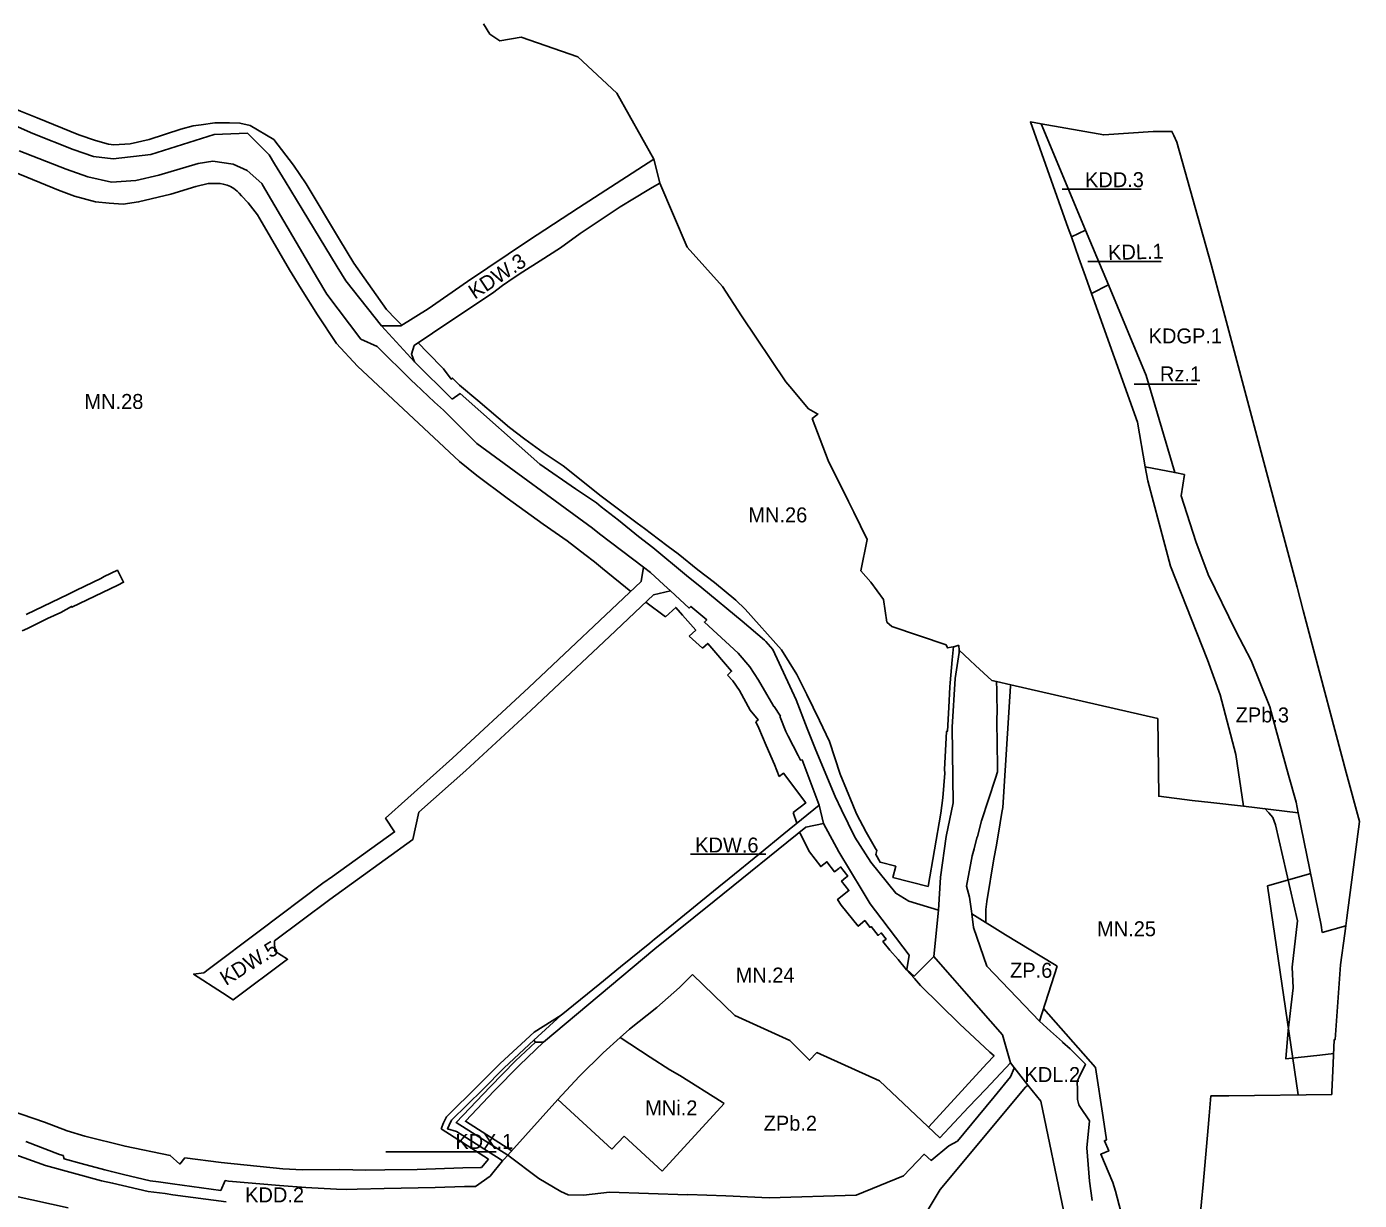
# Model space of a CAD drawing. Extents: x 7418991 to 7423142, y 5547704 to 5549547.
# Drawn here: x 7420035 to 7420480.5, y 5548551.2 to 5548943.4 of the extents above; entities that cross this region are included whole.
import ezdxf

# ---------------------------------------------------------------- set-up
doc = ezdxf.new("R2010")
doc.units = 0
for name, color, linetype in [('LIN_Linia Zabudowy Nieprzekraczalna', 7, 'Continuous'), ('LIN_linie_rozgraniczajace', 7, 'Continuous'), ('TRS_strefa ograniczen tunelu', 7, 'Continuous'), ('TXT_Oznaczenia_przeznaczen', 7, 'Continuous')]:
    doc.layers.add(name, color=color, linetype=linetype)

msp = doc.modelspace()

# ---------------------------------------------------------------- linework, layer by layer
at = {"layer": 'LIN_Linia Zabudowy Nieprzekraczalna'}
for p, q in [((7420248.59, 5548746.21), (7420241.92, 5548751.14)), ((7420260.87, 5548735.77), (7420256.47, 5548739.74)), ((7420279.77, 5548709.01), (7420278.76, 5548711.18)), ((7420282.17, 5548703.2), (7420279.77, 5548709.01)), ((7420292.45, 5548677.22), (7420291.24, 5548680.8)), ((7420189.36, 5548565.02), (7420173.52, 5548575.16)), ((7420187.02, 5548562.15), (7420189.36, 5548565.02))]:
    msp.add_line(p, q, dxfattribs=at)
for points in [[(7420022.61, 5548919.58), (7420030.2, 5548916.29), (7420032.93, 5548915.22), (7420038.5, 5548912.93), (7420052.44, 5548907.31), (7420057.96, 5548905.38), (7420062.32, 5548904.19), (7420064.15, 5548903.97), (7420069.56, 5548904.31), (7420075.9, 5548905.75), (7420086.49, 5548909.16)], [(7420086.49, 5548909.16), (7420090.64, 5548910.3), (7420093.26, 5548910.63), (7420097.86, 5548911.26), (7420102.81, 5548911.34), (7420106.29, 5548911.2), (7420109.65, 5548910.43), (7420117.58, 5548905.77)], [(7420117.58, 5548905.77), (7420124.15, 5548897.13), (7420128.46, 5548890.88), (7420139.53, 5548872.3), (7420144.32, 5548864.36)], [(7420236.92, 5548754.73), (7420227.53, 5548762.42), (7420224.79, 5548764.61), (7420221.57, 5548767.04), (7420215.71, 5548771.57), (7420207.67, 5548777.24), (7420195.64, 5548785.92), (7420185.42, 5548793.43), (7420179.71, 5548798.13), (7420145.56, 5548829.95), (7420138.55, 5548837.52), (7420132.23, 5548847.16), (7420126.76, 5548855.88), (7420122.8, 5548862.23), (7420112.91, 5548879.23), (7420112.11, 5548880.56), (7420108.98, 5548884.6), (7420106.82, 5548886.86), (7420106.04, 5548887.83), (7420105.36, 5548888.5), (7420104.28, 5548889.32), (7420103.16, 5548889.98), (7420101.95, 5548890.49), (7420100.7, 5548890.86), (7420099.62, 5548891.02), (7420095.7, 5548890.98), (7420091.48, 5548890.08), (7420083.16, 5548887.5), (7420072.38, 5548884.86), (7420067.26, 5548884.14), (7420062.54, 5548884.43), (7420057.96, 5548884.92), (7420050.94, 5548886.83), (7420045.62, 5548888.77), (7420026.39, 5548896.72)], [(7420144.32, 5548864.36), (7420155.26, 5548848.93), (7420158.44, 5548845.7), (7420160.37, 5548843.66)], [(7420165.88, 5548837.84), (7420168.98, 5548834.57), (7420174.34, 5548829.08), (7420176.89, 5548825.7), (7420177.33, 5548826.02), (7420179.62, 5548823.65), (7420185.78, 5548818.53), (7420192.55, 5548812.67), (7420196.43, 5548809.47), (7420201.46, 5548805.64), (7420207.68, 5548801.17), (7420214.3, 5548796.66), (7420227.06, 5548786.56), (7420239.03, 5548777.55), (7420241.49, 5548775.74), (7420246.15, 5548772.18), (7420249.46, 5548769.68), (7420252.73, 5548767.22), (7420259.32, 5548761.88), (7420264.92, 5548757.66), (7420272.01, 5548751.75), (7420275.13, 5548748.79), (7420287.28, 5548735.23), (7420292.47, 5548726.92), (7420295.81, 5548720.21), (7420300.03, 5548711.57), (7420303.32, 5548704.54), (7420306.92, 5548693.59), (7420311.16, 5548683.44), (7420312.39, 5548680.35), (7420315.62, 5548674.23), (7420318.68, 5548668.85), (7420319.15, 5548668.16)], [(7420256.47, 5548739.74), (7420258.63, 5548741.76), (7420254.17, 5548746.83), (7420251.96, 5548749.34), (7420248.59, 5548746.21)], [(7420269.22, 5548726.77), (7420270.65, 5548728.02), (7420262.67, 5548737.31), (7420260.87, 5548735.77)], [(7420336.39, 5548656.15), (7420340.59, 5548680.57), (7420341.25, 5548685.72), (7420341.92, 5548693.92), (7420341.85, 5548695.15), (7420342.47, 5548707.85), (7420342.78, 5548707.98), (7420343.21, 5548715.97), (7420343.57, 5548722.86), (7420343.67, 5548724.18), (7420344.39, 5548731.8), (7420344.85, 5548736.27)], [(7420276.86, 5548715.01), (7420273.32, 5548721.58), (7420271.01, 5548724.8), (7420269.22, 5548726.77)], [(7420363.94, 5548723.48), (7420363.91, 5548723.07), (7420363.67, 5548719.63), (7420361.35, 5548682.45), (7420361.18, 5548681.97), (7420361, 5548680.85), (7420360.45, 5548677.42), (7420359.24, 5548669.9), (7420358.29, 5548665.3), (7420355.94, 5548651.12), (7420355.59, 5548648.46), (7420355.63, 5548643.99)], [(7420278.76, 5548711.18), (7420279.49, 5548711.78), (7420276.86, 5548715.01)], [(7420286.52, 5548692.89), (7420285, 5548696.86), (7420282.17, 5548703.2)], [(7420291.24, 5548680.8), (7420295.43, 5548684.05), (7420287.93, 5548694.02), (7420286.52, 5548692.89)], [(7420471.99, 5548600.26), (7420467.24, 5548599.73), (7420455.92, 5548598.48), (7420456.74, 5548607.93), (7420458.33, 5548622.27), (7420458.04, 5548629.11), (7420459.76, 5548644.67), (7420452.41, 5548676.74), (7420451.53, 5548679.19), (7420450.27, 5548680.73), (7420448.77, 5548682.28)], [(7420336.48, 5548575.68), (7420341.46, 5548581.13), (7420355.97, 5548596.92), (7420358.35, 5548599.49), (7420356.98, 5548600.74), (7420346.77, 5548610.23), (7420333.74, 5548622.99), (7420331.74, 5548625.35), (7420329.14, 5548628.26), (7420326.32, 5548631.65), (7420323.48, 5548634.82), (7420321.22, 5548637.68), (7420322.29, 5548638.52), (7420320.63, 5548640.58), (7420319.6, 5548639.74), (7420317.24, 5548642.72), (7420316.93, 5548642.43), (7420315.16, 5548644.68), (7420312.99, 5548642.83), (7420307.26, 5548649.87), (7420306.08, 5548651.76), (7420309.85, 5548654.73), (7420307.38, 5548657.9), (7420308.85, 5548659.07), (7420309.47, 5548659.56), (7420307.08, 5548662.63), (7420306.44, 5548662.14), (7420304.98, 5548661.02), (7420302.48, 5548664.36), (7420300.43, 5548662.78), (7420296.68, 5548667.64), (7420293.59, 5548673.85), (7420293.43, 5548674.3)], [(7420319.15, 5548668.16), (7420318.8, 5548666.75), (7420320.26, 5548664.22), (7420325.51, 5548662.88), (7420324.57, 5548659.09), (7420336.39, 5548656.15)], [(7420173.52, 5548575.16), (7420174.36, 5548577.12), (7420175.28, 5548579.16), (7420186.04, 5548589.68), (7420193.23, 5548596.92), (7420204.59, 5548607.45), (7420213.62, 5548613.09)], [(7420374.87, 5548615.32), (7420392.3, 5548595.58), (7420394.85, 5548578.9), (7420395.98, 5548571.46), (7420395.24, 5548571.14), (7420396.71, 5548567.74), (7420394.04, 5548566.59), (7420398.11, 5548557.14), (7420398.97, 5548554.26), (7420402.53, 5548540.72), (7420403.2, 5548538.9), (7420404.26, 5548536.65), (7420405.58, 5548534.97), (7420408.13, 5548532.08), (7420410.13, 5548530.34), (7420410.95, 5548529.8), (7420423.29, 5548523.41), (7420431.15, 5548519.58), (7420439.54, 5548515.56)], [(7420207.72, 5548604.08), (7420199.75, 5548596.41), (7420191.31, 5548587.79), (7420181.67, 5548577.65), (7420197.14, 5548567.79)], [(7419981.5, 5548600.8), (7419992.1, 5548595.34), (7419997.1, 5548592.94), (7419998.04, 5548592.5), (7420006.38, 5548589.15), (7420010.64, 5548587.74), (7420040.89, 5548577.34), (7420048.53, 5548574.46), (7420054.4, 5548572.62), (7420067.89, 5548569.27), (7420082.96, 5548566.23), (7420086.13, 5548563.32), (7420087.87, 5548565.39), (7420099.95, 5548563.83)], [(7420099.95, 5548563.83), (7420120.62, 5548561.78), (7420127.14, 5548561.46), (7420139.62, 5548561.49), (7420148.34, 5548561.26), (7420154.7, 5548561.39), (7420165.51, 5548561.52), (7420180.8, 5548562.04), (7420186.64, 5548562.15), (7420187.02, 5548562.15)]]:
    msp.add_lwpolyline(points, dxfattribs=at)
at = {"layer": 'LIN_linie_rozgraniczajace'}
for p, q in [((7420032.47, 5548901.95), (7420048.13, 5548895.81)), ((7420048.13, 5548895.81), (7420055.41, 5548893.29)), ((7420071.43, 5548892.07), (7420079.12, 5548893.83)), ((7420055.41, 5548893.29), (7420063.37, 5548891.52)), ((7420063.37, 5548891.52), (7420071.43, 5548892.07)), ((7420113.57, 5548890.98), (7420113.82, 5548890.56)), ((7420113.82, 5548890.56), (7420132.24, 5548859.34)), ((7420384.22, 5548873.2), (7420388.96, 5548875.45)), ((7420132.24, 5548859.34), (7420135.36, 5548854.02)), ((7420135.36, 5548854.02), (7420146.74, 5548838.99)), ((7420390.96, 5548854.26), (7420396.59, 5548857.14)), ((7420153.63, 5548843.45), (7420160.03, 5548843.45)), ((7420146.74, 5548838.99), (7420152.16, 5548836.55)), ((7420418.77, 5548794.4), (7420408.9, 5548796.36)), ((7420241.14, 5548762.84), (7420240.4, 5548758.01)), ((7420244.49, 5548753.59), (7420250.2, 5548754.91)), ((7420460.03, 5548680.77), (7420441.72, 5548682.92)), ((7420136.31, 5548651.73), (7420117.84, 5548637.93)), ((7420339.78, 5548648.18), (7420338.24, 5548632.71)), ((7420475.96, 5548642.93), (7420468.03, 5548640.7)), ((7420117.84, 5548637.93), (7420117.98, 5548634.49)), ((7420204.57, 5548604.7), (7420205.11, 5548604.11)), ((7420365.01, 5548595.69), (7420363.87, 5548597.13)), ((7420369.71, 5548589.74), (7420365.01, 5548595.69)), ((7420386.84, 5548592.42), (7420386.15, 5548591.01)), ((7420212.59, 5548584.86), (7420230.62, 5548568.28)), ((7420247.38, 5548560.98), (7420268.14, 5548583.6)), ((7420230.62, 5548568.28), (7420234.7, 5548572.71)), ((7420234.7, 5548572.71), (7420247.38, 5548560.98)), ((7420099.84, 5548554.53), (7420101.33, 5548557.81)), ((7420101.33, 5548557.81), (7420102.41, 5548557.67)), ((7420048.85, 5548548.76), (7420031.14, 5548552.63)), ((7420268.75, 5548552.67), (7420256.05, 5548553.17)), ((7420283.14, 5548552.09), (7420268.75, 5548552.67))]:
    msp.add_line(p, q, dxfattribs=at)
for points in [[(7420187.72, 5548944.36), (7420189.78, 5548940.99), (7420193.14, 5548938.75), (7420200.25, 5548939.92), (7420219.25, 5548933.4), (7420232.28, 5548921.23), (7420244.58, 5548899.15), (7420246.62, 5548891.21), (7420246.63, 5548891.19), (7420255.83, 5548869.73), (7420267.57, 5548856.66), (7420273.97, 5548846.79), (7420288.8, 5548824.73), (7420290.08, 5548823.2), (7420296.36, 5548815.74), (7420299.51, 5548814), (7420297.61, 5548812.46), (7420302.96, 5548798.43), (7420309.68, 5548784.74), (7420311.45, 5548781.16), (7420315.91, 5548772.05), (7420313.83, 5548761.61), (7420317.22, 5548757.83), (7420321.41, 5548752.03), (7420322.5, 5548744.47), (7420324.15, 5548742.96), (7420342.32, 5548736.89), (7420342.75, 5548735.82), (7420345.23, 5548736.35), (7420346.3, 5548736.6), (7420346.62, 5548736.6), (7420346.67, 5548735.03), (7420350.29, 5548731.69), (7420352.15, 5548729.97), (7420357.63, 5548724.93), (7420359.15, 5548724.58), (7420363.94, 5548723.48), (7420413.08, 5548712.23), (7420413.45, 5548686.24), (7420424.58, 5548684.83), (7420430.85, 5548684.19), (7420441.72, 5548682.92), (7420439.14, 5548700.25), (7420433.98, 5548720.15), (7420429.76, 5548731.89), (7420417.31, 5548763.11), (7420417.31, 5548763.11), (7420409.72, 5548791.72), (7420408.9, 5548796.36), (7420406.28, 5548811.26), (7420390.96, 5548854.26), (7420388.92, 5548859.99), (7420386.74, 5548866.12), (7420384.22, 5548873.2), (7420383.17, 5548876.14), (7420370.54, 5548911.59), (7420374.15, 5548910.95), (7420395.06, 5548907.27), (7420411.6, 5548908.46), (7420417.81, 5548908.42), (7420418.45, 5548907.04), (7420419.49, 5548904.8), (7420430.95, 5548863.92), (7420434.62, 5548850.15), (7420459.65, 5548756.08), (7420461.72, 5548748.31), (7420463.74, 5548740.73), (7420476.12, 5548694.19), (7420480.48, 5548677.81), (7420476.31, 5548645.63), (7420475.96, 5548642.93), (7420475.63, 5548640.42), (7420474.14, 5548629.87), (7420472.37, 5548604.94), (7420472.09, 5548604.89), (7420471.59, 5548594.46), (7420471.31, 5548587.49), (7420471.27, 5548586.6), (7420436.83, 5548586.17), (7420430.86, 5548586.1), (7420430.26, 5548579.42), (7420429.92, 5548575.61), (7420428.22, 5548556.56), (7420427.18, 5548544.91)], [(7420037, 5548907.69), (7419994.04, 5548926.74), (7419977.79, 5548933.93), (7419969.89, 5548935.8), (7419962.51, 5548936.47), (7419951.22, 5548935.66), (7419947.24, 5548934.87)], [(7420037, 5548907.69), (7420050.55, 5548902.38), (7420057.32, 5548900.04)], [(7420057.32, 5548900.04), (7420063.93, 5548899.3), (7420076.53, 5548900.76), (7420097.7, 5548907.38), (7420108.81, 5548907.84)], [(7420108.81, 5548907.84), (7420110.02, 5548906.63), (7420115.99, 5548900.64), (7420117.78, 5548897.61)], [(7420468.03, 5548640.7), (7420467.73, 5548643.22), (7420460.03, 5548680.77), (7420459.32, 5548684.23), (7420456.84, 5548693.25), (7420454.73, 5548700.95), (7420452.61, 5548708.66), (7420450.57, 5548716.11), (7420444.3, 5548731.65), (7420439.24, 5548741.39), (7420429.92, 5548760.39), (7420425.8, 5548771.39), (7420420.93, 5548786.61), (7420422.03, 5548793.75), (7420418.77, 5548794.4), (7420409.2, 5548826.91), (7420396.59, 5548857.14), (7420392.74, 5548866.38), (7420388.96, 5548875.45), (7420374.15, 5548910.95)], [(7420113.57, 5548890.98), (7420108.74, 5548895.33), (7420104.05, 5548897.53), (7420097.23, 5548898.46), (7420092.34, 5548897.69), (7420079.12, 5548893.83)], [(7420160.03, 5548843.45), (7420169.18, 5548849.14), (7420182.39, 5548858.31), (7420202.69, 5548871.97), (7420219.47, 5548882.86), (7420244.58, 5548899.15)], [(7420164.68, 5548831.41), (7420153.63, 5548843.45), (7420141.63, 5548858.52), (7420138.74, 5548863.19), (7420127.05, 5548882.46), (7420121.43, 5548891.85), (7420117.78, 5548897.61)], [(7420164.54, 5548836.94), (7420176.81, 5548845.15), (7420190.74, 5548854.41), (7420194.1, 5548856.97), (7420197.94, 5548859.57), (7420200.82, 5548861.46), (7420206.59, 5548865.14), (7420213.4, 5548869.48), (7420219.96, 5548874.32), (7420224.4, 5548877.18), (7420233.35, 5548883.19), (7420238.21, 5548886.17), (7420242.38, 5548888.71), (7420244.06, 5548889.73), (7420246.63, 5548891.19)], [(7420152.16, 5548836.55), (7420163.64, 5548825.25), (7420164.97, 5548823.99), (7420171.34, 5548817.99), (7420174.3, 5548815.34), (7420185.48, 5548804.12)], [(7420164.68, 5548831.41), (7420163.67, 5548834), (7420164.54, 5548836.94)], [(7420164.68, 5548831.41), (7420177.22, 5548818.99)], [(7420206.51, 5548797.28), (7420179.92, 5548820.8), (7420177.22, 5548818.99)], [(7420248, 5548756.94), (7420243.57, 5548761), (7420241.14, 5548762.84), (7420226.5, 5548773.91), (7420224.14, 5548775.84), (7420185.48, 5548804.12)], [(7420206.51, 5548797.28), (7420218.48, 5548788.98), (7420225.45, 5548784.31), (7420227.02, 5548783.01), (7420232.77, 5548778.49), (7420239.47, 5548773.12), (7420244.25, 5548769.4)], [(7420281.62, 5548738.38), (7420274.2, 5548744.73), (7420260.65, 5548755.88), (7420255.52, 5548760.05), (7420244.25, 5548769.4)], [(7420033.45, 5548741.57), (7420035.26, 5548742.34), (7420041.99, 5548745.63), (7420046.35, 5548747.72), (7420049.97, 5548749.69), (7420050.11, 5548749.43), (7420052.6, 5548750.64), (7420065.46, 5548756.83), (7420067.37, 5548757.79), (7420065.3, 5548761.81), (7420060.94, 5548759.67), (7420059.77, 5548759.03), (7420051.61, 5548755.09), (7420048.98, 5548753.84), (7420034.77, 5548747.05)], [(7420112.69, 5548641.13), (7420134, 5548657.16), (7420137.19, 5548659.44), (7420157.98, 5548674.33), (7420154.98, 5548678.89), (7420177.32, 5548698.94), (7420202.87, 5548722.61), (7420240.4, 5548758.01)], [(7420248, 5548756.94), (7420250.2, 5548754.91), (7420256.47, 5548749.14), (7420257.02, 5548749.69), (7420262.31, 5548745.2), (7420261.54, 5548744.48), (7420272.83, 5548734.09), (7420276.78, 5548729.56), (7420279.58, 5548725.07), (7420282.4, 5548720.21), (7420284.75, 5548716.21), (7420284.84, 5548716.28), (7420286.97, 5548713), (7420286.76, 5548712.84), (7420286.87, 5548712.65)], [(7420136.31, 5548651.73), (7420164.07, 5548671.75), (7420166.13, 5548680.92), (7420181.79, 5548694.84), (7420203.55, 5548714.97), (7420209.45, 5548720.5), (7420229.87, 5548739.64), (7420244.49, 5548753.59)], [(7420292.2, 5548718.5), (7420284.46, 5548735.33), (7420282.12, 5548737.97), (7420281.62, 5548738.38)], [(7420346.67, 5548735.03), (7420346.69, 5548734.34), (7420345.42, 5548725.58), (7420344.33, 5548709.32), (7420344.66, 5548684.09), (7420342.31, 5548672.81), (7420340.48, 5548659.25), (7420339.78, 5548648.18), (7420329.89, 5548651.22), (7420325.49, 5548653.84), (7420317.18, 5548664.26), (7420311.83, 5548672.54), (7420307.38, 5548681.75), (7420305.23, 5548686.16), (7420298.84, 5548701.65), (7420295.86, 5548708.85), (7420292.2, 5548718.5)], [(7420359.15, 5548724.58), (7420359.28, 5548721.71), (7420359.32, 5548719.24), (7420359.4, 5548715.28), (7420359.3, 5548711.32)], [(7420294.26, 5548698.4), (7420293.69, 5548698.31), (7420292.9, 5548699.92), (7420289.57, 5548706.35), (7420288.79, 5548707.86), (7420286.87, 5548712.65)], [(7420359.3, 5548711.32), (7420359.51, 5548696.22), (7420359.53, 5548694.46), (7420358.82, 5548692.33), (7420354.16, 5548678.08), (7420352.86, 5548672.84), (7420352.6, 5548672.36), (7420351.68, 5548668.71), (7420351.07, 5548666.3), (7420349.11, 5548656.22), (7420350.2, 5548652.57)], [(7420294.26, 5548698.4), (7420299.92, 5548683.3), (7420301.38, 5548677.13), (7420306.43, 5548667.63), (7420314.26, 5548654.73), (7420316.9, 5548650.32), (7420318.7, 5548647.94), (7420329.98, 5548633.17), (7420329.16, 5548628.37), (7420331.61, 5548626.09), (7420338.24, 5548632.71), (7420338.89, 5548631.97), (7420344.47, 5548625.6), (7420348.38, 5548621.14), (7420361.15, 5548606.58), (7420363.87, 5548597.13)], [(7420299.92, 5548683.3), (7420288.09, 5548673.68), (7420279.94, 5548667.04), (7420269.83, 5548658.81), (7420266.34, 5548655.97), (7420264.61, 5548654.57), (7420246.97, 5548640.22), (7420244.86, 5548638.5), (7420243.25, 5548637.19), (7420233.48, 5548629.25), (7420226.58, 5548623.62), (7420213.62, 5548613.09), (7420204.57, 5548604.7), (7420194.62, 5548595.48), (7420187.45, 5548588.26), (7420176.95, 5548577.99), (7420176.19, 5548576.31), (7420175.66, 5548575.07), (7420178.63, 5548574.27), (7420193.22, 5548564.93), (7420194.03, 5548564.42)], [(7420195.78, 5548566.29), (7420178.55, 5548577.27), (7420189.87, 5548589.18), (7420198.35, 5548597.84), (7420205.11, 5548604.11), (7420207.72, 5548604.08), (7420226.38, 5548619.65), (7420244.99, 5548635.29), (7420264.75, 5548651.2), (7420295.46, 5548675.93), (7420301.38, 5548677.13)], [(7420350.2, 5548652.57), (7420350.8, 5548647.84), (7420350.92, 5548646.92), (7420351.5, 5548642.41), (7420356, 5548629.48)], [(7420379.44, 5548629.52), (7420378.58, 5548630.03), (7420362.22, 5548639.89), (7420350.92, 5548646.92)], [(7420117.98, 5548634.49), (7420122.21, 5548631.77), (7420103.97, 5548618.18), (7420100.41, 5548620.56), (7420090.79, 5548626.8), (7420094.15, 5548627.28), (7420096.09, 5548628.73), (7420112.69, 5548641.13)], [(7420257.54, 5548626.72), (7420255.09, 5548624.25), (7420253.16, 5548622.3), (7420245.61, 5548615.62), (7420236.51, 5548608.4), (7420233.37, 5548605.6), (7420227.73, 5548600.49), (7420219.62, 5548592.62)], [(7420257.54, 5548626.72), (7420271.71, 5548612.99), (7420290.15, 5548604.68), (7420296.66, 5548598.03), (7420299.15, 5548600.62), (7420320.08, 5548591.19), (7420340.23, 5548572.13), (7420349.86, 5548582.31), (7420355.62, 5548588.41), (7420363.87, 5548597.13)], [(7420386.84, 5548592.42), (7420388.91, 5548596.7), (7420383.81, 5548601.82), (7420381.27, 5548604.11), (7420381.24, 5548604.13), (7420377.28, 5548607.74), (7420373.53, 5548611.14), (7420356, 5548629.48)], [(7420373.53, 5548611.14), (7420379.44, 5548629.52)], [(7420268.14, 5548583.6), (7420267.44, 5548584.03), (7420253.33, 5548592.93), (7420249.97, 5548594.86), (7420243.39, 5548599.01), (7420233.37, 5548605.6)], [(7420365.01, 5548595.69), (7420365.1, 5548595.43), (7420363.9, 5548592.52), (7420358.37, 5548585.8), (7420353.03, 5548579.31), (7420346.2, 5548571), (7420343.22, 5548569.47), (7420337.36, 5548564.56), (7420335.01, 5548566.62), (7420328.06, 5548559.36), (7420312.3, 5548552.97), (7420283.14, 5548552.09)], [(7420219.62, 5548592.62), (7420212.59, 5548584.86), (7420195.78, 5548566.29)], [(7420390.22, 5548577.74), (7420386.99, 5548582.6), (7420386.67, 5548583.09), (7420386.27, 5548584.87), (7420386.21, 5548588.08), (7420386.15, 5548591.01)], [(7420331.09, 5548539.41), (7420340.34, 5548554.86), (7420368.87, 5548589.02), (7420369.71, 5548589.74)], [(7420393.66, 5548519.63), (7420388.35, 5548527.46), (7420385.38, 5548532.68), (7420383.66, 5548537.98), (7420381.72, 5548547.38), (7420373.96, 5548584.35), (7420369.71, 5548589.74)], [(7419990.07, 5548581.55), (7419990.27, 5548581.45), (7420001.88, 5548576.8), (7420029.78, 5548566.94), (7420041.31, 5548562.9), (7420059.95, 5548557.78), (7420063.71, 5548556.99), (7420075.61, 5548554.14)], [(7420391.14, 5548551.21), (7420390.22, 5548557.61), (7420389.34, 5548568.77), (7420390.22, 5548577.74)], [(7420034.67, 5548570.9), (7420045.99, 5548566.58), (7420047.18, 5548566.19), (7420047.54, 5548565.04), (7420053.19, 5548563.48), (7420061.12, 5548561.38), (7420063.33, 5548560.8), (7420067.38, 5548559.83), (7420076.27, 5548557.69), (7420079, 5548557.36), (7420083.76, 5548556.71), (7420099.84, 5548554.53)], [(7420195.78, 5548566.29), (7420194.57, 5548564.99), (7420194.03, 5548564.42), (7420189.89, 5548559.34), (7420184.98, 5548555.88)], [(7420213.58, 5548554.12), (7420206.16, 5548558.55), (7420195.78, 5548566.29)], [(7420154.48, 5548555.14), (7420145.42, 5548554.9), (7420142.06, 5548554.79), (7420138.59, 5548554.99), (7420128.34, 5548555.49), (7420119.48, 5548556.18), (7420102.41, 5548557.67)], [(7420184.98, 5548555.88), (7420181.34, 5548555.83), (7420171.55, 5548555.5), (7420154.48, 5548555.14)], [(7420081.26, 5548553.53), (7420075.61, 5548554.14)], [(7420101.65, 5548550.71), (7420083.87, 5548553.03), (7420081.26, 5548553.53)], [(7420256.05, 5548553.17), (7420255.87, 5548553.03), (7420229.77, 5548553.97), (7420221.17, 5548552.95), (7420216.05, 5548553), (7420213.58, 5548554.12)]]:
    msp.add_lwpolyline(points, dxfattribs=at)
at = {"layer": 'TRS_strefa ograniczen tunelu'}
msp.add_line((7420464.21, 5548660.4), (7420449.77, 5548656.33), dxfattribs=at)
msp.add_lwpolyline([(7420449.77, 5548656.33), (7420460.04, 5548586.46)], dxfattribs=at)
at = {"layer": 'TXT_Oznaczenia_przeznaczen'}
for p, q in [((7420381.16, 5548889.13), (7420407.57, 5548889.13)), ((7420389.69, 5548864.95), (7420414.28, 5548864.95)), ((7420405.2, 5548824), (7420426.16, 5548824)), ((7420256.91, 5548666.89), (7420282.03, 5548666.89)), ((7420191.89, 5548567.41), (7420155.07, 5548567.41))]:
    msp.add_line(p, q, dxfattribs=at)

# ---------------------------------------------------------------- texts
for s, rotation, p in [('KDD.3', 0.2787, (7420388.78, 5548889.75)), ('KDW.3', 33.4397, (7420184.77, 5548852.18)), ('KDL.1', 1.6501, (7420396.55, 5548865.43)), ('KDW.6', 359.9106, (7420258.45, 5548667.48)), ('KDW.5', 31.8465, (7420101.6, 5548622.81)), ('KDX.1', 0.1331, (7420178.29, 5548568.37))]:
    msp.add_text(s, height=5, rotation=rotation, dxfattribs=at).set_placement(p)
for s, p in [('KDGP.1', (7420410.05, 5548837.59)), ('Rz.1', (7420413.82, 5548824.91)), ('MN.28', (7420054.3, 5548815.69)), ('MN.26', (7420276.23, 5548777.79)), ('ZPb.3', (7420439.13, 5548710.93)), ('MN.25', (7420392.81, 5548639.47)), ('ZP.6', (7420363.72, 5548625.59)), ('MN.24', (7420271.99, 5548624.01)), ('KDL.2', (7420368.55, 5548590.75)), ('MNi.2', (7420241.74, 5548579.61)), ('ZPb.2', (7420281.35, 5548574.48)), ('KDD.2', (7420108.02, 5548550.54))]:
    msp.add_text(s, height=5, dxfattribs=at).set_placement(p)

doc.saveas('drawing.dxf')
